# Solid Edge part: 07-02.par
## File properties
Author: edge
Template: jis part.par
Last saved by: edge
Revision: 19
Application: Solid Edge
Density: 7833.000 kg/m^3
Accuracy: 0.990
文書内容のタイプ: 0
Material: 鋼鉄
面のスタイル: Bronze
塗りつぶしのスタイル: ANSI32(Steel)
バーチャルスタイル: 鋼鉄 機械仕上げ
Coef. of Thermal Exp: 0.0
Thermal Conductivity: 32.0
Specific Heat: 481.0
Modulus of Elasticity: 199947953000.0
Poisson's Ratio: 0.29
Yield Stress: 262000766.0
Ultimate Stress: 358527364.0
Elongation: 0.0
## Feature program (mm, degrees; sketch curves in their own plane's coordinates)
sketch for "unnamed Protrusion 1" plane through (0, 0, 0) normal (0, 0, 1) x-axis (1, 0, 0)
  line (-75, 60) -> (75, 60)
  line (75, 60) -> (75, -60)
  line (75, -60) -> (-75, -60)
  line (-75, -60) -> (-75, 60)
  dimension (linear) = 75
  dimension (linear) = 75
extrude "unnamed Protrusion 1" add finite 50 symmetric
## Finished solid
Body 1: solid body, 6 faces, 12 edges, 8 vertices.
  Faces by surface: plane 6
  Edges by curve: line 12
Bounding box of the edges (mm): 150.000 x 120.000 x 50.000, from (-75, -60, -25) to (75, 60, 25).
Planar faces by outward normal: +x 1, +y 1, +z 1, -x 1, -y 1, -z 1
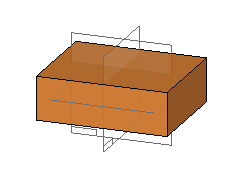
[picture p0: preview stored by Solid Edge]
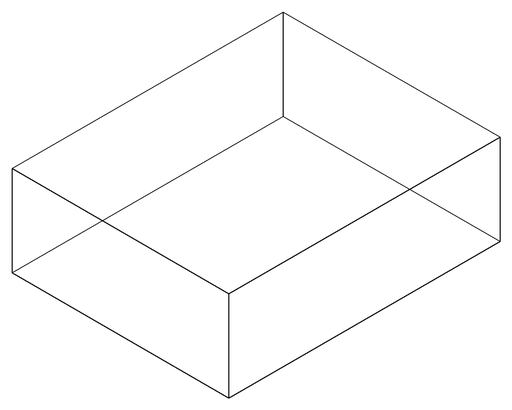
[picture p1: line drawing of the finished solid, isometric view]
